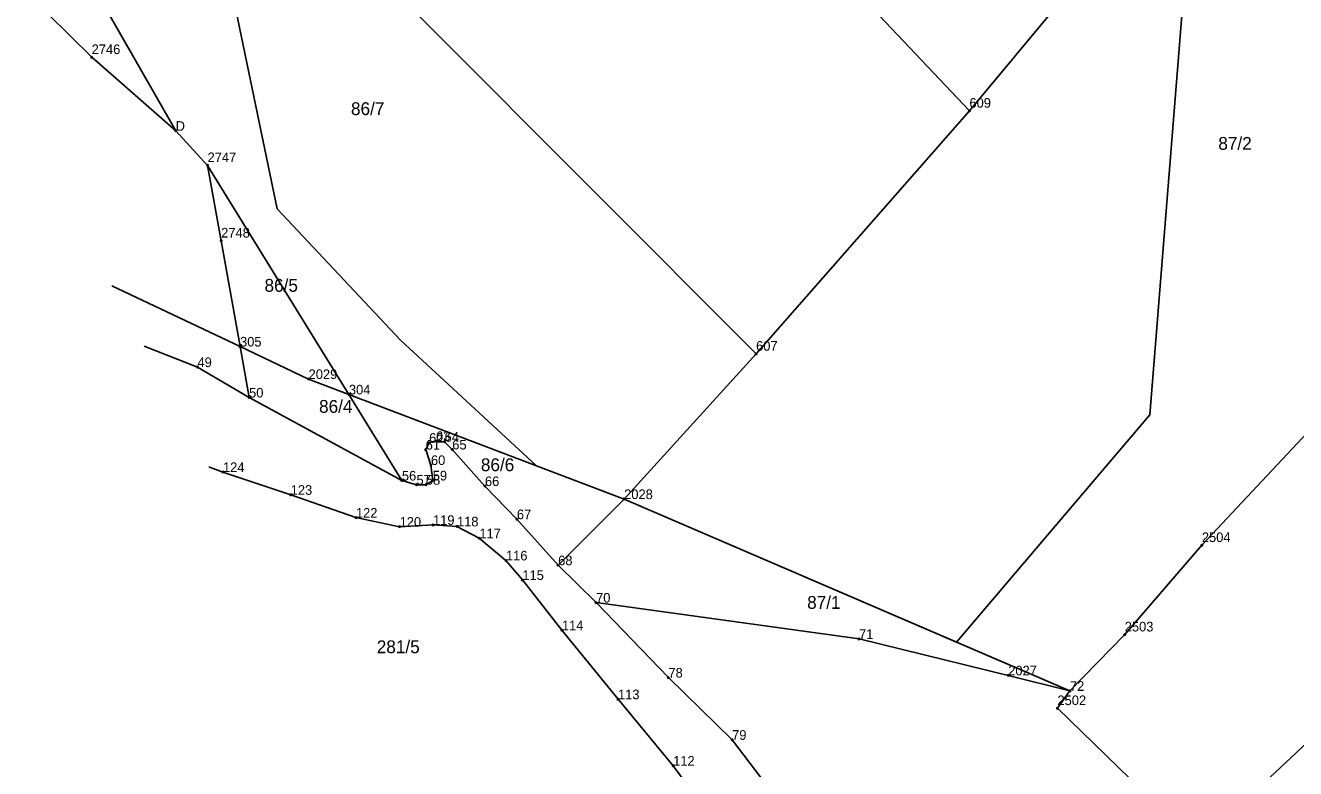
# Model space of a CAD drawing. Extents: x 7467189 to 7469366, y 5491487 to 5492734.
# Drawn here: x 7467461 to 7467609.4, y 5492014.5 to 5492101.3 of the extents above; entities that cross this region are included whole.
import ezdxf

# ---------------------------------------------------------------- set-up
doc = ezdxf.new("R2010")
doc.units = 0
for name, color, linetype in [('203-punkt graniczny', 7, 'Continuous'), ('203-punkt graniczny-Atr103', 7, 'Continuous'), ('211-numer działki ewidencyjnej', 7, 'Continuous'), ('217-kontur klasyfikacyjny', 7, 'Continuous'), ('218-kontur użytku gruntowego', 7, 'Continuous'), ('219-działka ewidencyjna', 7, 'Continuous')]:
    doc.layers.add(name, color=color, linetype=linetype)

# ---------------------------------------------------------------- blocks, each defined once
blk = doc.blocks.new('203')
blk.add_circle((0, 0), 0.09)

msp = doc.modelspace()

# ---------------------------------------------------------------- linework, layer by layer
at = {"layer": '217-kontur klasyfikacyjny'}
for points in [[(7467592.35, 5492055.83), (7467597.81, 5492123.91)], [(7467462.95, 5492116.3), (7467478.57, 5492089.02)], [(7467490.41, 5492079.89), (7467484.33, 5492109.2)], [(7467468.75, 5492097.6), (7467461.01, 5492105.31)], [(7467478.57, 5492089.02), (7467468.75, 5492097.6)], [(7467504.83, 5492064.54), (7467490.41, 5492079.89)], [(7467471.12, 5492070.91), (7467486.08, 5492063.8)], [(7467486.08, 5492063.8), (7467494.09, 5492060)], [(7467520.7, 5492049.87), (7467504.83, 5492064.54)], [(7467494.09, 5492060), (7467498.8, 5492058.2)], [(7467498.8, 5492058.2), (7467520.7, 5492049.87)], [(7467569.77, 5492029.26), (7467592.35, 5492055.83)], [(7467520.7, 5492049.87), (7467530.95, 5492045.97)], [(7467530.95, 5492045.97), (7467569.77, 5492029.26)], [(7467569.77, 5492029.26), (7467583.02, 5492023.56)], [(7467583.02, 5492023.56), (7467581.56, 5492021.52)], [(7467581.56, 5492021.52), (7467598.57, 5492004.96)]]:
    msp.add_lwpolyline(points, dxfattribs=at)
at = {"layer": '218-kontur użytku gruntowego'}
for points in [[(7467490.41, 5492079.89), (7467484.33, 5492109.2)], [(7467504.83, 5492064.54), (7467490.41, 5492079.89)], [(7467471.12, 5492070.91), (7467486.08, 5492063.8)], [(7467486.08, 5492063.8), (7467494.09, 5492060)], [(7467520.7, 5492049.87), (7467504.83, 5492064.54)], [(7467494.09, 5492060), (7467498.8, 5492058.2)], [(7467498.8, 5492058.2), (7467520.7, 5492049.87)], [(7467520.7, 5492049.87), (7467530.95, 5492045.97)], [(7467530.95, 5492045.97), (7467569.77, 5492029.26)], [(7467569.77, 5492029.26), (7467583.02, 5492023.56)], [(7467583.02, 5492023.56), (7467581.56, 5492021.52)], [(7467581.56, 5492021.52), (7467598.57, 5492004.96)]]:
    msp.add_lwpolyline(points, dxfattribs=at)
at = {"layer": '219-działka ewidencyjna'}
for points in [[(7467497.12, 5492169.74), (7467571.28, 5492091.34)], [(7467469.67, 5492139.9), (7467546.36, 5492062.93)], [(7467462.95, 5492116.3), (7467478.57, 5492089.02)], [(7467461.01, 5492105.31), (7467468.75, 5492097.6)], [(7467571.28, 5492091.34), (7467581.52, 5492103.64)], [(7467478.57, 5492089.02), (7467468.75, 5492097.6)], [(7467546.36, 5492062.93), (7467571.28, 5492091.34)], [(7467478.57, 5492089.02), (7467482.29, 5492084.97)], [(7467482.29, 5492084.97), (7467483.88, 5492076.17)], [(7467498.8, 5492058.2), (7467482.29, 5492084.97)], [(7467486.08, 5492063.8), (7467483.88, 5492076.17)], [(7467471.12, 5492070.91), (7467486.08, 5492063.8)], [(7467474.89, 5492063.85), (7467481.11, 5492061.4)], [(7467486.08, 5492063.8), (7467487.14, 5492057.84)], [(7467486.08, 5492063.8), (7467494.09, 5492060)], [(7467530.95, 5492045.97), (7467546.36, 5492062.93)], [(7467481.11, 5492061.4), (7467487.14, 5492057.84)], [(7467494.09, 5492060), (7467498.8, 5492058.2)], [(7467487.14, 5492057.84), (7467504.99, 5492048.14)], [(7467498.8, 5492058.2), (7467530.95, 5492045.97)], [(7467498.8, 5492058.2), (7467504.99, 5492048.14)], [(7467598.43, 5492040.57), (7467614.87, 5492058.1)], [(7467507.77, 5492051.75), (7467508.17, 5492052.55)], [(7467508.17, 5492052.55), (7467508.97, 5492052.76)], [(7467508.97, 5492052.76), (7467509.97, 5492052.67)], [(7467509.97, 5492052.67), (7467510.87, 5492051.77)], [(7467507.77, 5492051.75), (7467508.38, 5492049.95)], [(7467510.87, 5492051.77), (7467514.69, 5492047.49)], [(7467482.44, 5492049.74), (7467484.09, 5492049.13)], [(7467484.09, 5492049.13), (7467492, 5492046.47)], [(7467508.38, 5492049.95), (7467508.59, 5492048.15)], [(7467504.99, 5492048.14), (7467506.69, 5492047.65)], [(7467506.69, 5492047.65), (7467507.79, 5492047.65)], [(7467507.79, 5492047.65), (7467508.59, 5492048.15)], [(7467514.69, 5492047.49), (7467518.42, 5492043.62)], [(7467492, 5492046.47), (7467499.62, 5492043.8)], [(7467523.24, 5492038.24), (7467530.95, 5492045.97)], [(7467530.95, 5492045.97), (7467583.02, 5492023.56)], [(7467499.62, 5492043.8), (7467504.72, 5492042.74)], [(7467504.72, 5492042.74), (7467508.62, 5492042.95)], [(7467508.62, 5492042.95), (7467511.42, 5492042.78)], [(7467518.42, 5492043.62), (7467523.24, 5492038.24)], [(7467511.42, 5492042.78), (7467514.03, 5492041.39)], [(7467514.03, 5492041.39), (7467517.14, 5492038.8)], [(7467589.42, 5492030.13), (7467598.43, 5492040.57)], [(7467605.73, 5492012.85), (7467635.43, 5492040.66)], [(7467517.14, 5492038.8), (7467519.06, 5492036.52)], [(7467523.24, 5492038.24), (7467527.67, 5492033.87)], [(7467519.06, 5492036.52), (7467523.68, 5492030.64)], [(7467527.67, 5492033.87), (7467536.12, 5492025.11)], [(7467527.67, 5492033.87), (7467558.39, 5492029.63)], [(7467523.68, 5492030.64), (7467530.23, 5492022.58)], [(7467558.39, 5492029.63), (7467575.81, 5492025.37)], [(7467583.02, 5492023.56), (7467589.42, 5492030.13)], [(7467536.12, 5492025.11), (7467543.56, 5492017.84)], [(7467575.81, 5492025.37), (7467583.02, 5492023.56)], [(7467530.23, 5492022.58), (7467536.67, 5492014.81)], [(7467583.02, 5492023.56), (7467581.56, 5492021.52)], [(7467581.56, 5492021.52), (7467598.57, 5492004.96)], [(7467543.56, 5492017.84), (7467551.11, 5492007.89)], [(7467536.67, 5492014.81), (7467545.84, 5492002.46)]]:
    msp.add_lwpolyline(points, dxfattribs=at)

# ---------------------------------------------------------------- block references
at = {"layer": '203-punkt graniczny'}
for p in [(7467468.75, 5492097.6), (7467571.28, 5492091.34), (7467478.57, 5492089.02), (7467482.29, 5492084.97), (7467483.88, 5492076.17), (7467486.08, 5492063.8), (7467546.36, 5492062.93), (7467481.11, 5492061.4), (7467494.09, 5492060), (7467487.14, 5492057.84), (7467498.8, 5492058.2), (7467507.77, 5492051.75), (7467508.17, 5492052.55), (7467508.97, 5492052.76), (7467509.97, 5492052.67), (7467510.87, 5492051.77), (7467484.09, 5492049.13), (7467508.38, 5492049.95), (7467504.99, 5492048.14), (7467506.69, 5492047.65), (7467507.79, 5492047.65), (7467508.59, 5492048.15), (7467514.69, 5492047.49), (7467492, 5492046.47), (7467530.95, 5492045.97), (7467499.62, 5492043.8), (7467508.62, 5492042.95), (7467518.42, 5492043.62), (7467504.72, 5492042.74), (7467511.42, 5492042.78), (7467514.03, 5492041.39), (7467598.43, 5492040.57), (7467517.14, 5492038.8), (7467523.24, 5492038.24), (7467519.06, 5492036.52), (7467527.67, 5492033.87), (7467523.68, 5492030.64), (7467558.39, 5492029.63), (7467589.42, 5492030.13), (7467536.12, 5492025.11), (7467575.81, 5492025.37), (7467583.02, 5492023.56), (7467530.23, 5492022.58), (7467581.56, 5492021.52), (7467543.56, 5492017.84), (7467536.67, 5492014.81)]:
    msp.add_blockref('203', p, dxfattribs=at)

# ---------------------------------------------------------------- texts
at = {"layer": '203-punkt graniczny-Atr103'}
for s, height, p in [('2746', 1.125, (7467468.75, 5492097.98)), ('609', 1.125, (7467571.28, 5492091.71)), ('D', 1.12, (7467478.57, 5492089.02)), ('2747', 1.125, (7467482.29, 5492085.35)), ('2748', 1.125, (7467483.88, 5492076.54)), ('305', 1.125, (7467486.08, 5492063.8)), ('607', 1.125, (7467546.36, 5492063.31)), ('49', 1.125, (7467481.11, 5492061.4)), ('2029', 1.125, (7467494.09, 5492060)), ('304', 1.125, (7467498.8, 5492058.2)), ('50', 1.125, (7467487.14, 5492057.84)), ('62', 1.125, (7467508.17, 5492052.55)), ('63', 1.125, (7467508.97, 5492052.76)), ('64', 1.125, (7467509.97, 5492052.67)), ('61', 1.125, (7467507.77, 5492051.75)), ('65', 1.125, (7467510.87, 5492051.77)), ('60', 1.125, (7467508.38, 5492049.95)), ('124', 1.125, (7467484.09, 5492049.13)), ('56', 1.125, (7467504.99, 5492048.14)), ('59', 1.125, (7467508.59, 5492048.15)), ('123', 1.125, (7467492, 5492046.47)), ('57', 1.125, (7467506.69, 5492047.65)), ('58', 1.125, (7467507.79, 5492047.65)), ('66', 1.125, (7467514.69, 5492047.49)), ('2028', 1.125, (7467530.95, 5492045.97)), ('122', 1.125, (7467499.62, 5492043.8)), ('67', 1.125, (7467518.42, 5492043.62)), ('120', 1.125, (7467504.72, 5492042.74)), ('119', 1.125, (7467508.62, 5492042.95)), ('118', 1.125, (7467511.42, 5492042.78)), ('117', 1.125, (7467514.03, 5492041.39)), ('2504', 1.125, (7467598.43, 5492040.95)), ('116', 1.125, (7467517.14, 5492038.8)), ('68', 1.125, (7467523.24, 5492038.24)), ('115', 1.125, (7467519.06, 5492036.52)), ('70', 1.125, (7467527.67, 5492033.87)), ('114', 1.125, (7467523.68, 5492030.64)), ('2503', 1.125, (7467589.42, 5492030.5)), ('71', 1.125, (7467558.39, 5492029.63)), ('78', 1.125, (7467536.12, 5492025.11)), ('2027', 1.125, (7467575.81, 5492025.37)), ('113', 1.125, (7467530.23, 5492022.58)), ('72', 1.125, (7467583.02, 5492023.56)), ('2502', 1.125, (7467581.56, 5492021.89)), ('79', 1.125, (7467543.56, 5492017.84)), ('112', 1.125, (7467536.67, 5492014.81))]:
    msp.add_text(s, height=height, dxfattribs=at).set_placement(p)
at = {"layer": '211-numer działki ewidencyjnej'}
for s, p in [('86/7', (7467499.04, 5492090.85)), ('87/2', (7467600.35, 5492086.79)), ('86/5', (7467488.94, 5492070.2)), ('86/4', (7467495.31, 5492056.05)), ('86/6', (7467514.21, 5492049.23)), ('87/1', (7467552.32, 5492033.14)), ('281/5', (7467502.05, 5492027.96))]:
    msp.add_text(s, height=1.5, dxfattribs=at).set_placement(p)

doc.saveas('drawing.dxf')
